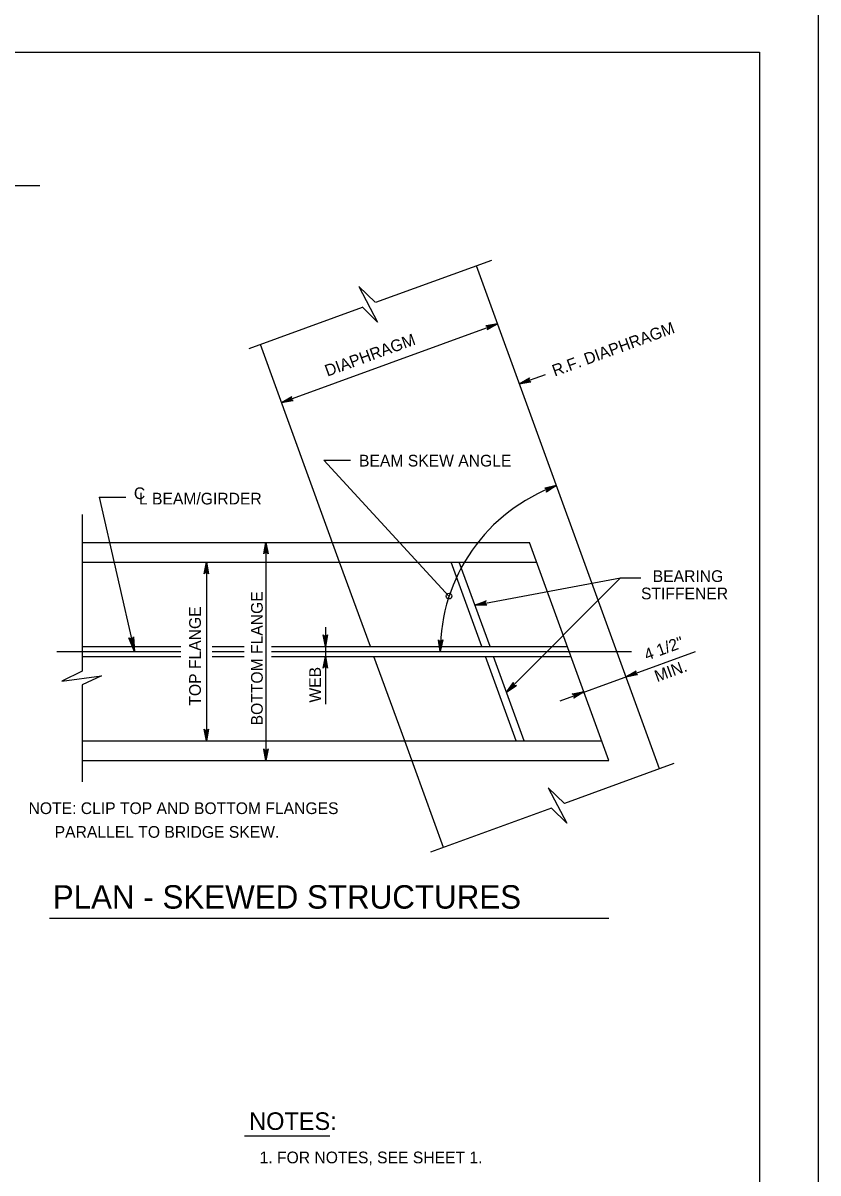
# Model space of a CAD drawing. Extents: x 640009 to 641706, y 298547 to 299735.
# Drawn here: x 640646.9 to 640850.5, y 298839.2 to 299133.7 of the extents above; entities that cross this region are included whole.
import ezdxf

# ---------------------------------------------------------------- set-up
doc = ezdxf.new("R2010")
doc.units = 0
doc.layers.add('1', color=7, linetype='Continuous')
doc.layers.add('PLT-BNDY', color=7, linetype='Continuous')

msp = doc.modelspace()

# ---------------------------------------------------------------- linework, layer by layer
at = {"layer": '1'}
for p, q in [((640049.47, 299126.17), (640835.47, 299126.17)), ((640049.47, 299126.17), (640835.47, 299126.17)), ((640835.47, 299126.17), (640835.47, 298562.17)), ((640835.47, 299126.17), (640835.47, 298562.17)), ((640651.24, 299091.94), (640529.49, 299091.94)), ((640766.87, 299072.89), (640737.16, 299062.08)), ((640809.87, 298942.69), (640763, 299071.48)), ((640733.79, 299060.85), (640704.72, 299050.27)), ((640713.12, 299036.51), (640768.4, 299056.63)), ((640728, 298995.63), (640707.72, 299051.36)), ((640774, 299041.26), (640780.74, 299043.71)), ((640723.91, 299021.7), (640730.76, 299021.7)), ((640723.91, 299021.7), (640756.08, 298986.87)), ((640666.43, 299012.3), (640675.5, 298972.67)), ((640666.43, 299012.3), (640673.28, 299012.3)), ((640662.05, 299007.86), (640662.05, 298967.71)), ((640662.05, 299000.7), (640776.59, 299000.7)), ((640709.11, 299000.7), (640709.11, 298944.82)), ((640796.93, 298944.82), (640776.59, 299000.7)), ((640662.05, 298995.63), (640778.44, 298995.63)), ((640693.87, 298995.63), (640693.87, 298949.9)), ((640735.86, 298974.03), (640728, 298995.63)), ((640764.37, 298974.03), (640756.51, 298995.63)), ((640766.5, 298974.03), (640758.64, 298995.63)), ((640762.65, 298984.61), (640799.89, 298991.59)), ((640799.89, 298991.59), (640770.76, 298962.32)), ((640799.89, 298991.59), (640805.15, 298991.59)), ((640724.35, 298978.95), (640724.35, 298959.27)), ((640655.63, 298972.76), (640687.32, 298972.76)), ((640662.05, 298974.03), (640687.32, 298974.03)), ((640662.05, 298971.49), (640687.32, 298971.49)), ((640695.34, 298974.03), (640703.57, 298974.03)), ((640695.34, 298972.76), (640703.57, 298972.76)), ((640695.34, 298971.49), (640703.57, 298971.49)), ((640710.59, 298974.03), (640786.3, 298974.03)), ((640710.59, 298972.76), (640802.71, 298972.76)), ((640710.59, 298971.49), (640787.23, 298971.49)), ((640744.65, 298949.9), (640736.79, 298971.49)), ((640773.16, 298949.9), (640765.3, 298971.49)), ((640775.28, 298949.9), (640767.43, 298971.49)), ((640784.44, 298960.16), (640819.07, 298972.77)), ((640662.05, 298964.19), (640662.05, 298939.42)), ((640662.05, 298949.9), (640795.08, 298949.9)), ((640754.59, 298922.57), (640744.65, 298949.9)), ((640662.05, 298944.82), (640796.93, 298944.82)), ((640813.6, 298944.05), (640785.58, 298933.85)), ((640782.27, 298932.65), (640751.25, 298921.36)), ((640653.68, 298904.5), (640796.91, 298904.5)), ((640703.63, 298848.74), (640725.49, 298848.74))]:
    msp.add_line(p, q, dxfattribs=at)
for points in [[(640737.07, 299062.17), (640732.91, 299066.18), (640737.68, 299057.11), (640733.76, 299060.97)], [(640768.4, 299056.63), (640765.79, 299055.08), (640765.87, 299055.2), (640765.95, 299055.31), (640765.97, 299055.43), (640766, 299055.54), (640765.98, 299055.64), (640765.96, 299055.74), (640765.91, 299055.83), (640765.86, 299055.92), (640765.77, 299055.99), (640765.68, 299056.06), (640765.54, 299056.1), (640765.41, 299056.13), (640768.4, 299056.63), (640765.54, 299056.1), (640765.68, 299056.06), (640768.4, 299056.63), (640765.77, 299055.99), (640765.86, 299055.92), (640768.4, 299056.63), (640765.91, 299055.83), (640765.96, 299055.74), (640768.4, 299056.63), (640765.98, 299055.64), (640766, 299055.54), (640768.4, 299056.63), (640765.97, 299055.43), (640765.95, 299055.31), (640768.4, 299056.63), (640765.87, 299055.2)], [(640774, 299041.26), (640776.61, 299042.8), (640776.53, 299042.69), (640776.45, 299042.58), (640776.43, 299042.46), (640776.4, 299042.35), (640776.42, 299042.25), (640776.44, 299042.15), (640776.49, 299042.06), (640776.54, 299041.97), (640776.63, 299041.9), (640776.72, 299041.82), (640776.86, 299041.79), (640776.99, 299041.75), (640774, 299041.26), (640776.86, 299041.79), (640776.72, 299041.82), (640774, 299041.26), (640776.63, 299041.9), (640776.54, 299041.97), (640774, 299041.26), (640776.49, 299042.06), (640776.44, 299042.15), (640774, 299041.26), (640776.42, 299042.25), (640776.4, 299042.35), (640774, 299041.26), (640776.43, 299042.46), (640776.45, 299042.58), (640774, 299041.26), (640776.53, 299042.69)], [(640713.12, 299036.51), (640715.74, 299038.06), (640715.65, 299037.94), (640715.57, 299037.83), (640715.55, 299037.71), (640715.53, 299037.6), (640715.55, 299037.5), (640715.57, 299037.4), (640715.62, 299037.31), (640715.67, 299037.22), (640715.76, 299037.15), (640715.85, 299037.08), (640715.98, 299037.04), (640716.12, 299037), (640713.12, 299036.51), (640715.98, 299037.04), (640715.85, 299037.08), (640713.12, 299036.51), (640715.76, 299037.15), (640715.67, 299037.22), (640713.12, 299036.51), (640715.62, 299037.31), (640715.57, 299037.4), (640713.12, 299036.51), (640715.55, 299037.5), (640715.53, 299037.6), (640713.12, 299036.51), (640715.55, 299037.71), (640715.57, 299037.83), (640713.12, 299036.51), (640715.65, 299037.94)], [(640783.47, 299015.22), (640780.93, 299013.57), (640781, 299013.69), (640781.08, 299013.81), (640781.1, 299013.92), (640781.11, 299014.04), (640781.09, 299014.13), (640781.07, 299014.23), (640781.01, 299014.32), (640780.96, 299014.41), (640780.87, 299014.48), (640780.78, 299014.55), (640780.64, 299014.58), (640780.5, 299014.61), (640783.47, 299015.22), (640780.64, 299014.58), (640780.78, 299014.55), (640783.47, 299015.22), (640780.87, 299014.48), (640780.96, 299014.41), (640783.47, 299015.22), (640781.01, 299014.32), (640781.07, 299014.23), (640783.47, 299015.22), (640781.09, 299014.13), (640781.11, 299014.04), (640783.47, 299015.22), (640781.1, 299013.92), (640781.08, 299013.81), (640783.47, 299015.22), (640781, 299013.69)], [(640709.11, 299000.7), (640709.67, 298997.72), (640709.59, 298997.84), (640709.51, 298997.95), (640709.41, 298998.01), (640709.31, 298998.07), (640709.21, 298998.09), (640709.11, 298998.1), (640709.01, 298998.09), (640708.91, 298998.07), (640708.81, 298998.01), (640708.71, 298997.95), (640708.63, 298997.84), (640708.55, 298997.72), (640709.11, 299000.7), (640708.63, 298997.84), (640708.71, 298997.95), (640709.11, 299000.7), (640708.81, 298998.01), (640708.91, 298998.07), (640709.11, 299000.7), (640709.01, 298998.09), (640709.11, 298998.1), (640709.11, 299000.7), (640709.21, 298998.09), (640709.31, 298998.07), (640709.11, 299000.7), (640709.41, 298998.01), (640709.51, 298997.95), (640709.11, 299000.7), (640709.59, 298997.84)], [(640693.87, 298995.63), (640694.43, 298992.64), (640694.35, 298992.76), (640694.27, 298992.87), (640694.17, 298992.93), (640694.07, 298992.99), (640693.97, 298993.01), (640693.87, 298993.03), (640693.77, 298993.01), (640693.67, 298992.99), (640693.57, 298992.93), (640693.47, 298992.87), (640693.39, 298992.76), (640693.31, 298992.64), (640693.87, 298995.63), (640693.39, 298992.76), (640693.47, 298992.87), (640693.87, 298995.63), (640693.57, 298992.93), (640693.67, 298992.99), (640693.87, 298995.63), (640693.77, 298993.01), (640693.87, 298993.03), (640693.87, 298995.63), (640693.97, 298993.01), (640694.07, 298992.99), (640693.87, 298995.63), (640694.17, 298992.93), (640694.27, 298992.87), (640693.87, 298995.63), (640694.35, 298992.76)], [(640762.65, 298984.61), (640765.48, 298985.71), (640765.38, 298985.61), (640765.28, 298985.51), (640765.24, 298985.4), (640765.2, 298985.3), (640765.2, 298985.19), (640765.21, 298985.09), (640765.24, 298985), (640765.28, 298984.9), (640765.35, 298984.82), (640765.43, 298984.73), (640765.56, 298984.67), (640765.69, 298984.61), (640762.65, 298984.61), (640765.56, 298984.67), (640765.43, 298984.73), (640762.65, 298984.61), (640765.35, 298984.82), (640765.28, 298984.9), (640762.65, 298984.61), (640765.24, 298985), (640765.21, 298985.09), (640762.65, 298984.61), (640765.2, 298985.19), (640765.2, 298985.3), (640762.65, 298984.61), (640765.24, 298985.4), (640765.28, 298985.51), (640762.65, 298984.61), (640765.38, 298985.61)], [(640675.14, 298976.31), (640674.91, 298976.12), (640675.5, 298972.67), (640675.14, 298976.31), (640675.25, 298976.53), (640675.5, 298972.67), (640674.55, 298976.03), (640674.27, 298976.1), (640675.5, 298972.67), (640674.06, 298976.25), (640674.27, 298976.1)], [(640724.35, 298974.03), (640723.79, 298977.02), (640723.87, 298976.9), (640723.95, 298976.79), (640724.05, 298976.73), (640724.15, 298976.67), (640724.25, 298976.65), (640724.35, 298976.63), (640724.45, 298976.65), (640724.55, 298976.67), (640724.65, 298976.73), (640724.75, 298976.79), (640724.83, 298976.9), (640724.91, 298977.02), (640724.35, 298974.03), (640724.83, 298976.9), (640724.75, 298976.79), (640724.35, 298974.03), (640724.65, 298976.73), (640724.55, 298976.67), (640724.35, 298974.03), (640724.45, 298976.65), (640724.35, 298976.63), (640724.35, 298974.03), (640724.25, 298976.65), (640724.15, 298976.67), (640724.35, 298974.03), (640724.05, 298976.73), (640723.95, 298976.79), (640724.35, 298974.03), (640723.87, 298976.9)], [(640753.74, 298972.76), (640753.27, 298975.76), (640753.35, 298975.64), (640753.42, 298975.53), (640753.52, 298975.47), (640753.62, 298975.4), (640753.72, 298975.38), (640753.82, 298975.36), (640753.92, 298975.38), (640754.02, 298975.39), (640754.12, 298975.45), (640754.22, 298975.5), (640754.31, 298975.62), (640754.39, 298975.73), (640753.74, 298972.76), (640754.31, 298975.62), (640754.22, 298975.5), (640753.74, 298972.76), (640754.12, 298975.45), (640754.02, 298975.39), (640753.74, 298972.76), (640753.92, 298975.38), (640753.82, 298975.36), (640753.74, 298972.76), (640753.72, 298975.38), (640753.62, 298975.4), (640753.74, 298972.76), (640753.52, 298975.47), (640753.42, 298975.53), (640753.74, 298972.76), (640753.35, 298975.64)], [(640724.35, 298971.49), (640724.91, 298968.51), (640724.83, 298968.63), (640724.75, 298968.74), (640724.65, 298968.8), (640724.55, 298968.86), (640724.45, 298968.88), (640724.35, 298968.89), (640724.25, 298968.88), (640724.15, 298968.86), (640724.05, 298968.8), (640723.95, 298968.74), (640723.87, 298968.63), (640723.79, 298968.51), (640724.35, 298971.49), (640723.87, 298968.63), (640723.95, 298968.74), (640724.35, 298971.49), (640724.05, 298968.8), (640724.15, 298968.86), (640724.35, 298971.49), (640724.25, 298968.88), (640724.35, 298968.89), (640724.35, 298971.49), (640724.45, 298968.88), (640724.55, 298968.86), (640724.35, 298971.49), (640724.65, 298968.8), (640724.75, 298968.74), (640724.35, 298971.49), (640724.83, 298968.63)], [(640662.05, 298967.71), (640656.86, 298965.17), (640667.01, 298966.55), (640662.05, 298964.19)], [(640801.28, 298966.3), (640803.89, 298967.84), (640803.81, 298967.73), (640803.73, 298967.61), (640803.71, 298967.5), (640803.69, 298967.38), (640803.71, 298967.28), (640803.72, 298967.18), (640803.77, 298967.1), (640803.83, 298967.01), (640803.91, 298966.94), (640804, 298966.86), (640804.14, 298966.83), (640804.28, 298966.79), (640801.28, 298966.3), (640804.14, 298966.83), (640804, 298966.86), (640801.28, 298966.3), (640803.91, 298966.94), (640803.83, 298967.01), (640801.28, 298966.3), (640803.77, 298967.1), (640803.72, 298967.18), (640801.28, 298966.3), (640803.71, 298967.28), (640803.69, 298967.38), (640801.28, 298966.3), (640803.71, 298967.5), (640803.73, 298967.61), (640801.28, 298966.3), (640803.81, 298967.73)], [(640770.76, 298962.32), (640772.49, 298964.82), (640772.46, 298964.68), (640772.44, 298964.54), (640772.47, 298964.43), (640772.49, 298964.32), (640772.55, 298964.23), (640772.61, 298964.15), (640772.69, 298964.09), (640772.78, 298964.03), (640772.89, 298964), (640773, 298963.97), (640773.14, 298964), (640773.28, 298964.02), (640770.76, 298962.32), (640773.14, 298964), (640773, 298963.97), (640770.76, 298962.32), (640772.89, 298964), (640772.78, 298964.03), (640770.76, 298962.32), (640772.69, 298964.09), (640772.61, 298964.15), (640770.76, 298962.32), (640772.55, 298964.23), (640772.49, 298964.32), (640770.76, 298962.32), (640772.47, 298964.43), (640772.44, 298964.54), (640770.76, 298962.32), (640772.46, 298964.68)], [(640790.54, 298962.39), (640787.93, 298960.84), (640788.01, 298960.95), (640788.09, 298961.07), (640788.11, 298961.18), (640788.13, 298961.3), (640788.12, 298961.4), (640788.1, 298961.5), (640788.05, 298961.59), (640788, 298961.67), (640787.91, 298961.75), (640787.82, 298961.82), (640787.68, 298961.86), (640787.55, 298961.89), (640790.54, 298962.39), (640787.68, 298961.86), (640787.82, 298961.82), (640790.54, 298962.39), (640787.91, 298961.75), (640788, 298961.67), (640790.54, 298962.39), (640788.05, 298961.59), (640788.1, 298961.5), (640790.54, 298962.39), (640788.12, 298961.4), (640788.13, 298961.3), (640790.54, 298962.39), (640788.11, 298961.18), (640788.09, 298961.07), (640790.54, 298962.39), (640788.01, 298960.95)], [(640693.87, 298949.9), (640693.31, 298952.88), (640693.39, 298952.77), (640693.47, 298952.65), (640693.57, 298952.59), (640693.67, 298952.54), (640693.77, 298952.52), (640693.87, 298952.5), (640693.97, 298952.52), (640694.07, 298952.54), (640694.17, 298952.59), (640694.27, 298952.65), (640694.35, 298952.77), (640694.43, 298952.88), (640693.87, 298949.9), (640694.35, 298952.77), (640694.27, 298952.65), (640693.87, 298949.9), (640694.17, 298952.59), (640694.07, 298952.54), (640693.87, 298949.9), (640693.97, 298952.52), (640693.87, 298952.5), (640693.87, 298949.9), (640693.77, 298952.52), (640693.67, 298952.54), (640693.87, 298949.9), (640693.57, 298952.59), (640693.47, 298952.65), (640693.87, 298949.9), (640693.39, 298952.77)], [(640709.11, 298944.82), (640708.55, 298947.81), (640708.63, 298947.69), (640708.71, 298947.58), (640708.81, 298947.52), (640708.91, 298947.46), (640709.01, 298947.44), (640709.11, 298947.42), (640709.21, 298947.44), (640709.31, 298947.46), (640709.41, 298947.52), (640709.51, 298947.58), (640709.59, 298947.69), (640709.67, 298947.81), (640709.11, 298944.82), (640709.59, 298947.69), (640709.51, 298947.58), (640709.11, 298944.82), (640709.41, 298947.52), (640709.31, 298947.46), (640709.11, 298944.82), (640709.21, 298947.44), (640709.11, 298947.42), (640709.11, 298944.82), (640709.01, 298947.44), (640708.91, 298947.46), (640709.11, 298944.82), (640708.81, 298947.52), (640708.71, 298947.58), (640709.11, 298944.82), (640708.63, 298947.69)], [(640785.58, 298933.85), (640781.42, 298937.86), (640786.19, 298928.79), (640782.27, 298932.65)]]:
    msp.add_lwpolyline(points, dxfattribs=at)
msp.add_circle((640756.01, 298986.94), 0.724, dxfattribs=at)
msp.add_arc((640798.93, 298972.76), 45.18, 110, 180, dxfattribs=at)
at = {"layer": 'PLT-BNDY'}
msp.add_lwpolyline([(640009.47, 299141.17), (640850.47, 299141.17), (640850.47, 298547.17), (640009.47, 298547.17)], close=True, dxfattribs=at)

# ---------------------------------------------------------------- texts
at = {"layer": '1'}
for s, rotation, p in [('R.F. DIAPHRAGM', 20, (640783.06, 299043.13)), (' DIAPHRAGM', 20, (640723.81, 299042.73)), ('BOTTOM FLANGE', 90, (640708.31, 298953.84)), ('TOP FLANGE', 90, (640692.47, 298958.89)), ('4 1/2"', 20, (640806.63, 298970.38)), ('WEB', 90, (640723.2, 298959.67)), ('MIN.', 20, (640809.28, 298964.88))]:
    msp.add_text(s, height=3, rotation=rotation, dxfattribs=at).set_placement(p)
for s, height, p in [('BEAM SKEW ANGLE', 3, (640732.96, 299020.12)), ('C', 3, (640675.32, 299011.77)), ('L BEAM/GIRDER', 3, (640676.62, 299010.4)), ('BEARING', 3, (640808.16, 298990.55)), ('STIFFENER', 3, (640805.16, 298986.11)), ('NOTE: CLIP TOP AND BOTTOM FLANGES', 3, (640648.35, 298931.13)), ('      PARALLEL TO BRIDGE SKEW.', 3, (640648.35, 298925.06)), ('PLAN - SKEWED STRUCTURES', 6, (640654.54, 298906.92)), ('NOTES:', 4.5, (640704.84, 298850.26)), ('1. FOR NOTES, SEE SHEET 1.', 3, (640707.5, 298841.71))]:
    msp.add_text(s, height=height, dxfattribs=at).set_placement(p)

doc.saveas('drawing.dxf')
